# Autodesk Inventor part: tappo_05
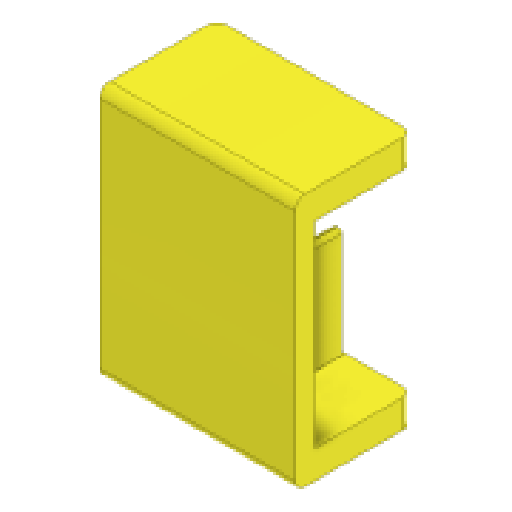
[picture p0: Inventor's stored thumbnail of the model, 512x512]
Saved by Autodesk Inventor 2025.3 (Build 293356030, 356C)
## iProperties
Created: 2026-02
Part Number: tappo_05
Material: Generico
Document SubType Name: Modeling
Designer: R5800u
Density: 1 g/cm^3
Appearance: Giallo canarino
Author: R5800u
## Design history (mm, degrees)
sketch "Schizzo1"
  geometry: L1 (10, 10)-(-10, 10); L2 (-10, 10)-(-10, -10); L3 (-10, -10)-(10, -10); L4 (10, -10)-(10, 10); L5 (10, 10)-(-10, -10); L6 (-10, 10)-(10, -10); L7 (6, -8)-(3, -8) reference; L8 (6, -7.061)-(6, -8) reference; L9 (2.939, -4)-(6, -7.061) reference; L10 (0, 0)-(0, -10); L11 (2.939, -4)-(0, -4); L12 (3, -8)-(0, -8); L13 (0, -7.8)-(3, -7.8); L14 (3, -7.8)-(5.8, -7.8); L15 (5.8, -7.8)-(5.8, -7.144); L16 (5.8, -7.144)-(2.856, -4.2); L17 (2.856, -4.2)-(0, -4.2); L18 (0, -7.8)-(-3, -7.8); L19 (-3, -7.8)-(-5.8, -7.8); L20 (-5.8, -7.8)-(-5.8, -7.144); L21 (-5.8, -7.144)-(-2.856, -4.2); L22 (-2.856, -4.2)-(0, -4.2)
  constraints: 38 end point, 4 symmetric about line, 3 midpoint, 3 perpendicular, 2 parallel, 2 point on line, 1 horizontal, 4 other
  dimensions: "d0" = 20 distance of L3.end L2.end; "d1" = 20 distance of L2.end L1.end; "d2" = 0.2 distance between parallel lines of L12 L13
  node "Riferimento1"
  node "Riferimento2"
  node "Riferimento3"
extrude "Estrusione1" new body sketch "Schizzo1" distance "d3" = 2; taper "d4" = 0 deg
extrude "Estrusione2" new body sketch "Schizzo1" distance "d5" = 1.9; taper "d6" = 0 deg; dims "d11" = 5, "d12" = 0
pattern_circular "Serie circolare1" dims angle "d8" = 360 deg
fillet "Raccordo2" dims "d13" = 0.4
sketch "Schizzo2"
  geometry: 1 further point
hole "Foro1" sketch "Schizzo2" at (0, 0) diameter "d14" = 4.3; stored, may be unused: countersink angle "d18" = 90 deg, drill point angle "d20" = 118 deg; dims "d15" = 6, "d16" = 8, "d17" = 4.6, "d19" = 8
fillet "Raccordo3" dims "d21" = 1
sketch "Schizzo3"
  geometry: L1 (0, 0)-(20, 0) reference; L2 (20, 0)-(20, 2) reference; L3 (0, 2)-(20, 2) reference; L4 (0, 0)-(0, 2) reference; 1 further point
extrude "Estrusione3" join sketch "Schizzo3" distance "d22" = 3; taper "d23" = 0 deg
sketch "Schizzo4"
  geometry: L1 (-10, -13)-(10, -13) reference; L2 (-10, 10)-(-10, -13) reference; L3 (10, -13)-(-10, -13); L4 (-10, -13)-(-10, -10.1); L5 (-10, -10.1)-(10, -10.1); L6 (10, -10.1)-(10, -13); 2 further points
  constraints: 8 end point, 2 parallel, 1 horizontal, 1 perpendicular, 1 point on line
  dimensions: "d24" = 2.9 distance of L3.end L4.end
extrude "Estrusione4" join sketch "Schizzo4" distance "d25" = 10; taper "d26" = 0 deg
fillet "Raccordo4" dims "d27" = 1
mirror "Speculare1"
node "Solido1"
node "Solido2"
node "Linea chiusa proiettata1"
